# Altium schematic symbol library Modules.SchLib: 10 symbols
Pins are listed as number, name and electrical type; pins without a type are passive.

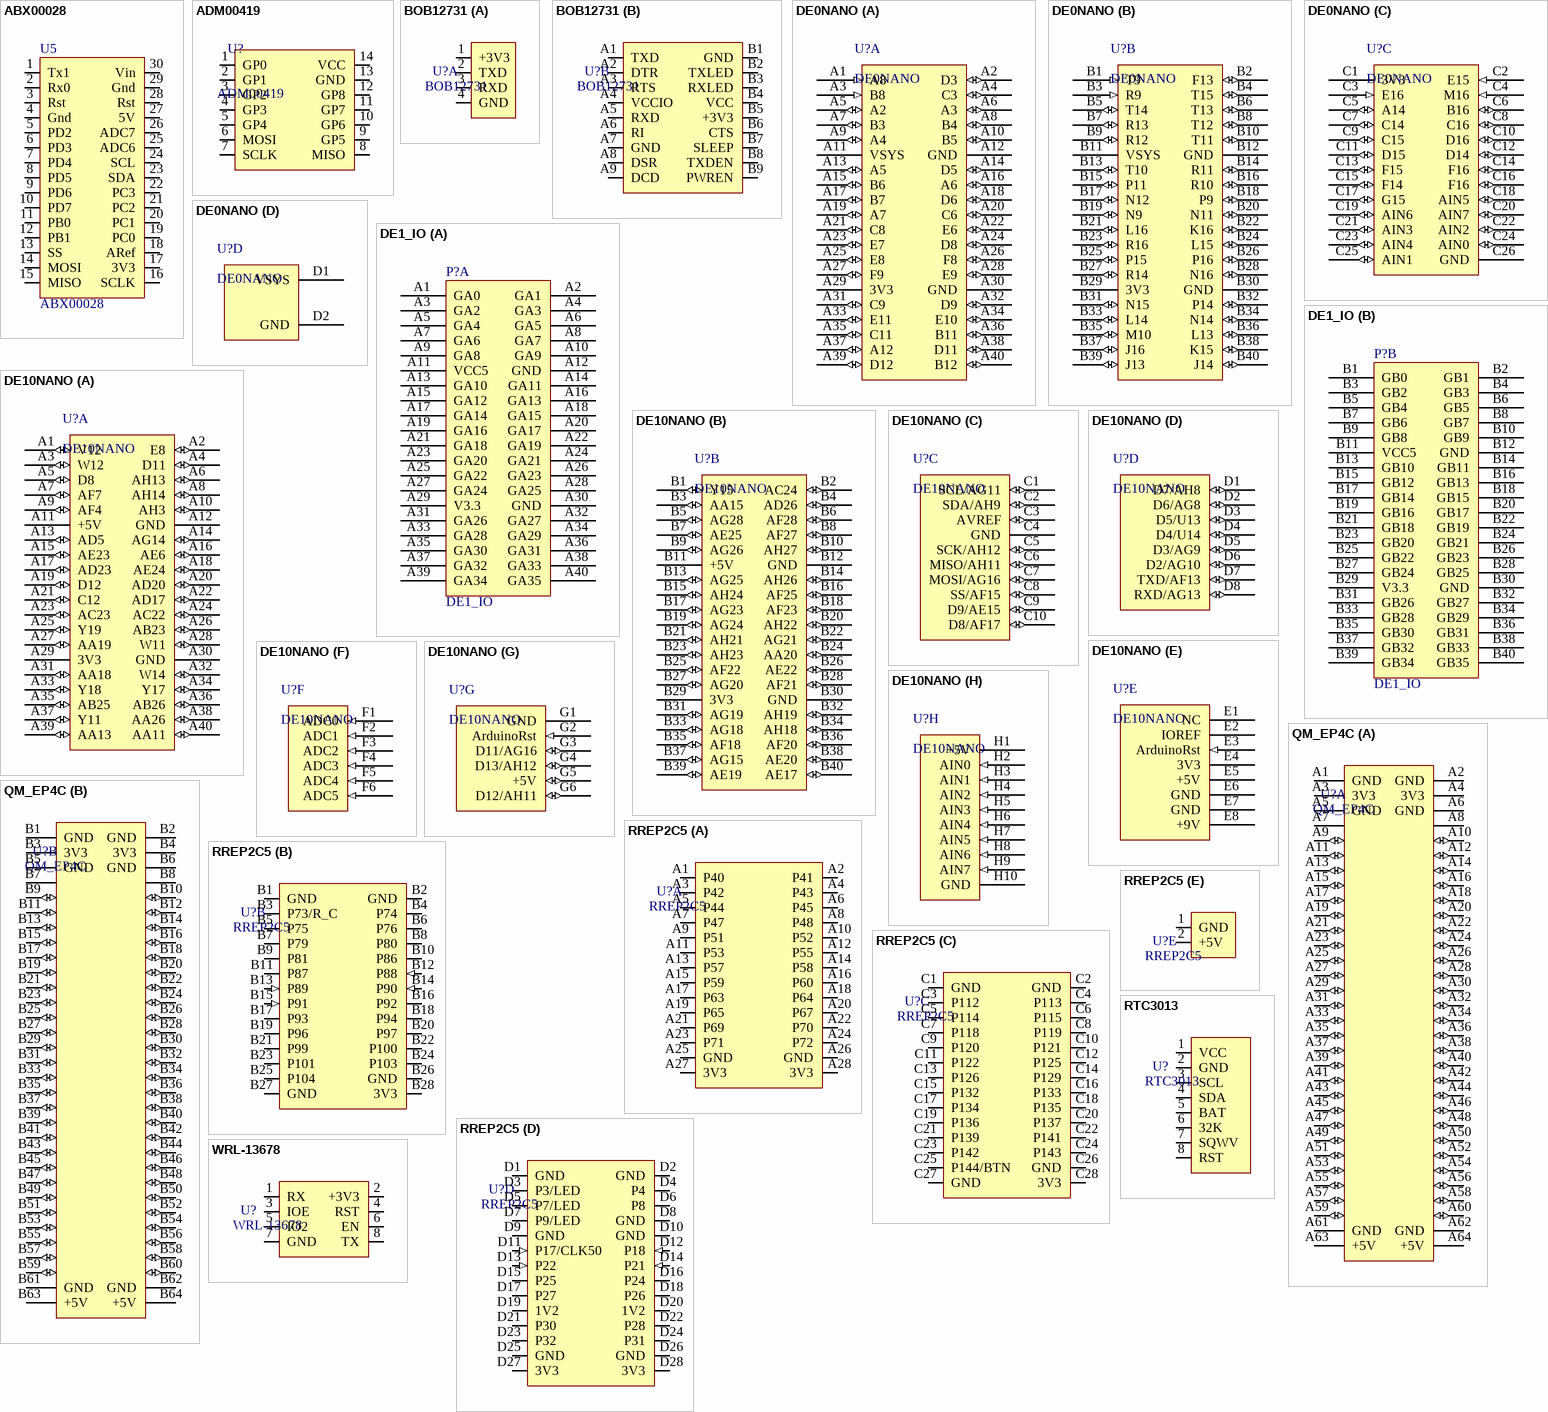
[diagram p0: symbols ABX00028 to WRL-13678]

## ABX00028
designator U5
ATmega4809 Arduino Nano Every AVR® AVR MCU 8-Bit Embedded Evaluation Board; DK PN: 1050-ABX00028-ND
footprint ARDUINO_NANO
pins: 1 Tx1, 2 Rx0, 3 Rst, 4 Gnd (power), 5 PD2, 6 PD3, 7 PD4, 8 PD5, 9 PD6, 10 PD7, 11 PB0, 12 PB1, 13 SS, 14 MOSI, 15 MISO, 16 SCLK, 17 3V3 (power), 18 ARef, 19 PC0, 20 PC1, 21 PC2, 22 PC3, 23 SDA, 24 SCL, 25 ADC6, 26 ADC7, 27 5V (power), 28 Rst, 29 Gnd, 30 Vin

## ADM00419
designator U?
MCP2210 USB to SPI Interface Evaluation Board; DK PN: ADM00419-ND; MFG: Microchip
footprint MCP2210DEV
pins: 1 GP0, 2 GP1, 3 GP2, 4 GP3, 5 GP4, 6 MOSI, 7 SCLK, 8 MISO, 9 GP5, 10 GP6, 11 GP7, 12 GP8, 13 GND, 14 VCC

## BOB12731
designator U?
FT232R USB 2.0 to UART Interface Evaluation Board; MFG: SparkFun; MFG PN: BOB-12731; DK PN: 1568-1195-ND
footprint BOB12731
part A pins: 1 +3V3, 2 TXD, 3 RXD, 4 GND
part B pins: A1 TXD, A2 DTR, A3 RTS, A4 VCCIO, A5 RXD, A6 RI, A7 GND, A8 DSR, A9 DCD, B1 GND, B2 TXLED, B3 RXLED, B4 VCC, B5 +3V3, B6 CTS, B7 SLEEP, B8 TXDEN, B9 PWREN

## DE0NANO
designator U?
footprint DE0NANO
part A pins: A1 A8 (in), A2 D3 (io), A3 B8 (in), A4 C3 (io), A5 A2 (io), A6 A3 (io), A7 B3 (io), A8 B4 (io), A9 A4 (io), A10 B5 (io), A11 VSYS (power), A12 GND (power), A13 A5 (io), A14 D5 (io), A15 B6 (io), A16 A6 (io), A17 B7 (io), A18 D6 (io), A19 A7 (io), A20 C6 (io), A21 C8 (io), A22 E6 (io), A23 E7 (io), A24 D8 (io), A25 E8 (io), A26 F8 (io), A27 F9 (io), A28 E9 (io), A29 3V3 (power), A30 GND (power), A31 C9 (io), A32 D9 (io), A33 E11 (io), A34 E10 (io), A35 C11 (io), A36 B11 (io), A37 A12 (io), A38 D11 (io), A39 D12 (io), A40 B12 (io)
part B pins: B1 T9 (in), B2 F13 (io), B3 R9 (in), B4 T15 (io), B5 T14 (io), B6 T13 (io), B7 R13 (io), B8 T12 (io), B9 R12 (io), B10 T11 (io), B11 VSYS (power), B12 GND (power), B13 T10 (io), B14 R11 (io), B15 P11 (io), B16 R10 (io), B17 N12 (io), B18 P9 (io), B19 N9 (io), B20 N11 (io), B21 L16 (io), B22 K16 (io), B23 R16 (io), B24 L15 (io), B25 P15 (io), B26 P16 (io), B27 R14 (io), B28 N16 (io), B29 3V3 (power), B30 GND (power), B31 N15 (io), B32 P14 (io), B33 L14 (io), B34 N14 (io), B35 M10 (io), B36 L13 (io), B37 J16 (io), B38 K15 (io), B39 J13 (io), B40 J14 (io)
part C pins: C1 3V3 (power), C2 E15 (in), C3 E16 (in), C4 M16 (in), C5 A14 (io), C6 B16 (io), C7 C14 (io), C8 C16 (io), C9 C15 (io), C10 D16 (io), C11 D15 (io), C12 D14 (io), C13 F15 (io), C14 F16 (io), C15 F14 (io), C16 F16 (io), C17 G15 (io), C18 AIN5 (io), C19 AIN6 (io), C20 AIN7 (io), C21 AIN3 (io), C22 AIN2 (io), C23 AIN4 (io), C24 AIN0 (io), C25 AIN1 (io), C26 GND (power)
part D pins: D1 VSYS (power), D2 GND (power)

## DE1_IO
designator P?
footprint DE1_IO
part A pins: A1 GA0, A2 GA1, A3 GA2, A4 GA3, A5 GA4, A6 GA5, A7 GA6, A8 GA7, A9 GA8, A10 GA9, A11 VCC5, A12 GND, A13 GA10, A14 GA11, A15 GA12, A16 GA13, A17 GA14, A18 GA15, A19 GA16, A20 GA17, A21 GA18, A22 GA19, A23 GA20, A24 GA21, A25 GA22, A26 GA23, A27 GA24, A28 GA25, A29 V3.3, A30 GND, A31 GA26, A32 GA27, A33 GA28, A34 GA29, A35 GA30, A36 GA31, A37 GA32, A38 GA33, A39 GA34, A40 GA35
part B pins: B1 GB0, B2 GB1, B3 GB2, B4 GB3, B5 GB4, B6 GB5, B7 GB6, B8 GB7, B9 GB8, B10 GB9, B11 VCC5, B12 GND, B13 GB10, B14 GB11, B15 GB12, B16 GB13, B17 GB14, B18 GB15, B19 GB16, B20 GB17, B21 GB18, B22 GB19, B23 GB20, B24 GB21, B25 GB22, B26 GB23, B27 GB24, B28 GB25, B29 V3.3, B30 GND, B31 GB26, B32 GB27, B33 GB28, B34 GB29, B35 GB30, B36 GB31, B37 GB32, B38 GB33, B39 GB34, B40 GB35

## DE10NANO
designator U?
DE10-NANO CYCLONE V SE SOC KIT; MFG PN: P0496; DK PN: P0496-ND; MFG: Terasic
footprint DE10NANO (DE10 Nano Module)
part A pins: A1 V12 (io), A2 E8 (io), A3 W12 (io), A4 D11 (io), A5 D8 (io), A6 AH13 (io), A7 AF7 (io), A8 AH14 (io), A9 AF4 (io), A10 AH3 (io), A11 +5V (power), A12 GND (power), A13 AD5 (io), A14 AG14 (io), A15 AE23 (io), A16 AE6 (io), A17 AD23 (io), A18 AE24 (io), A19 D12 (io), A20 AD20 (io), A21 C12 (io), A22 AD17 (io), A23 AC23 (io), A24 AC22 (io), A25 Y19 (io), A26 AB23 (io), A27 AA19 (io), A28 W11 (io), A29 3V3 (power), A30 GND (power), A31 AA18 (io), A32 W14 (io), A33 Y18 (io), A34 Y17 (io), A35 AB25 (io), A36 AB26 (io), A37 Y11 (io), A38 AA26 (io), A39 AA13 (io), A40 AA11 (io)
part B pins: B1 Y15 (io), B2 AC24 (io), B3 AA15 (io), B4 AD26 (io), B5 AG28 (io), B6 AF28 (io), B7 AE25 (io), B8 AF27 (io), B9 AG26 (io), B10 AH27 (io), B11 +5V (power), B12 GND (power), B13 AG25 (io), B14 AH26 (io), B15 AH24 (io), B16 AF25 (io), B17 AG23 (io), B18 AF23 (io), B19 AG24 (io), B20 AH22 (io), B21 AH21 (io), B22 AG21 (io), B23 AH23 (io), B24 AA20 (io), B25 AF22 (io), B26 AE22 (io), B27 AG20 (io), B28 AF21 (io), B29 3V3 (power), B30 GND (power), B31 AG19 (io), B32 AH19 (io), B33 AG18 (io), B34 AH18 (io), B35 AF18 (io), B36 AF20 (io), B37 AG15 (io), B38 AE20 (io), B39 AE19 (io), B40 AE17 (io)
part C pins: C1 SCL/AG11 (io), C2 SDA/AH9 (io), C3 AVREF (io), C4 GND (power), C5 SCK/AH12 (io), C6 MISO/AH11 (io), C7 MOSI/AG16 (io), C8 SS/AF15 (io), C9 D9/AE15 (io), C10 D8/AF17 (io)
part D pins: D1 D7/AH8 (io), D2 D6/AG8 (io), D3 D5/U13 (io), D4 D4/U14 (io), D5 D3/AG9 (io), D6 D2/AG10 (io), D7 TXD/AF13 (io), D8 RXD/AG13 (io)
part E pins: E1 NC, E2 IOREF, E3 ArduinoRst (in), E4 3V3 (power), E5 +5V (power), E6 GND (power), E7 GND (power), E8 +9V (power)
part F pins: F1 ADC0 (in), F2 ADC1 (in), F3 ADC2 (in), F4 ADC3 (in), F5 ADC4 (in), F6 ADC5 (in)
part G pins: G1 GND (power), G2 ArduinoRst (in), G3 D11/AG16 (io), G4 D13/AH12 (io), G5 +5V (io), G6 D12/AH11 (io)
part H pins: H1 +5V (power), H2 AIN0 (in), H3 AIN1 (in), H4 AIN2 (in), H5 AIN3 (in), H6 AIN4 (in), H7 AIN5 (in), H8 AIN6 (in), H9 AIN7 (in), H10 GND (power)

## QM_EP4C
designator U?
footprint QMTECH_EP4CE15
part A pins: A1 GND (power), A2 GND (power), A3 3V3 (power), A4 3V3 (power), A5 GND (power), A6 GND (power), A7, A8, A9 (io), A10 (io), A11 (io), A12 (io), A13 (io), A14 (io), A15 (io), A16 (io), A17 (io), A18 (io), A19 (io), A20 (io), A21 (io), A22 (io), A23 (io), A24 (io), A25 (io), A26 (io), A27 (io), A28 (io), A29 (io), A30 (io), A31 (io), A32 (io), A33 (io), A34 (io), A35 (io), A36 (io), A37 (io), A38 (io), A39 (io), A40 (io), A41 (io), A42 (io), A43 (io), A44 (io), A45 (io), A46 (io), A47 (io), A48 (io), A49 (io), A50 (io), A51 (io), A52 (io), A53 (io), A54 (io), A55 (io), A56 (io), A57 (io), A58 (io), A59 (io), A60 (io), A61 GND (power), A62 GND (power), A63 +5V (power), A64 +5V (power)
part B pins: B1 GND (power), B2 GND (power), B3 3V3 (power), B4 3V3 (power), B5 GND (power), B6 GND (power), B7, B8, B9 (io), B10 (io), B11 (io), B12 (io), B13 (io), B14 (io), B15 (io), B16 (io), B17 (io), B18 (io), B19 (io), B20 (io), B21 (io), B22 (io), B23 (io), B24 (io), B25 (io), B26 (io), B27 (io), B28 (io), B29 (io), B30 (io), B31 (io), B32 (io), B33 (io), B34 (io), B35 (io), B36 (io), B37 (io), B38 (io), B39 (io), B40 (io), B41 (io), B42 (io), B43 (io), B44 (io), B45 (io), B46 (io), B47 (io), B48 (io), B49 (io), B50 (io), B51 (io), B52 (io), B53 (io), B54 (io), B55 (io), B56 (io), B57 (io), B58 (io), B59 (io), B60 (io), B61 GND (power), B62 GND (power), B63 +5V (power), B64 +5V (power)

## RREP2C5
designator U?
RioRand EP2C5T144 Altera Cyclone II FPGA Mini Development Board
footprint RR2C5
part A pins: A1 P40 (io), A2 P41 (io), A3 P42 (io), A4 P43 (io), A5 P44 (io), A6 P45 (io), A7 P47 (io), A8 P48 (io), A9 P51 (io), A10 P52 (io), A11 P53 (io), A12 P55 (io), A13 P57 (io), A14 P58 (io), A15 P59 (io), A16 P60 (io), A17 P63 (io), A18 P64 (io), A19 P65 (io), A20 P67 (io), A21 P69 (io), A22 P70 (io), A23 P71 (io), A24 P72 (io), A25 GND (power), A26 GND (power), A27 3V3 (power), A28 3V3 (power)
part B pins: B1 GND (power), B2 GND (power), B3 P73/R_C (io), B4 P74 (io), B5 P75 (io), B6 P76 (io), B7 P79 (io), B8 P80 (io), B9 P81 (io), B10 P86 (io), B11 P87 (io), B12 P88 (in), B13 P89 (in), B14 P90 (in), B15 P91 (in), B16 P92 (io), B17 P93 (io), B18 P94 (io), B19 P96 (io), B20 P97 (io), B21 P99 (io), B22 P100 (io), B23 P101 (io), B24 P103 (io), B25 P104 (io), B26 GND (power), B27 GND (power), B28 3V3 (power)
part C pins: C1 GND (power), C2 GND (power), C3 P112 (io), C4 P113 (io), C5 P114 (io), C6 P115 (io), C7 P118 (io), C8 P119 (io), C9 P120 (io), C10 P121 (io), C11 P122 (io), C12 P125 (io), C13 P126 (io), C14 P129 (io), C15 P132 (io), C16 P133 (io), C17 P134 (io), C18 P135 (io), C19 P136 (io), C20 P137 (io), C21 P139 (io), C22 P141 (io), C23 P142 (io), C24 P143 (io), C25 P144/BTN (io), C26 GND, C27 GND (power), C28 3V3 (power)
part D pins: D1 GND (power), D2 GND (power), D3 P3/LED (io), D4 P4 (io), D5 P7/LED (io), D6 P8 (io), D7 P9/LED (io), D8 GND (power), D9 GND (power), D10 GND (power), D11 P17/CLK50 (in), D12 P18 (in), D13 P22 (in), D14 P21 (in), D15 P25 (io), D16 P24 (io), D17 P27 (io), D18 P26 (io), D19 1V2 (power), D20 1V2 (power), D21 P30 (io), D22 P28 (io), D23 P32 (io), D24 P31 (io), D25 GND (power), D26 GND (power), D27 3V3 (power), D28 3V3 (power)
part E pins: 1 GND (power), 2 +5V (power)

## RTC3013
designator U?
DS3231 Real Time Clock (RTC) Timing Evaluation Board; MFG: AdaFruit; MFG PN: 3013; DK PN: 1528-1598-ND
footprint RTC3013
pins: 1 VCC, 2 GND, 3 SCL, 4 SDA, 5 BAT, 6 32K, 7 SQWV, 8 RST

## WRL-13678
designator U?
WiFi 802.11b/g/n Transceiver Module 2.4GHz ~ 2.48GHz Integrated, Trace Through Hole; MFG: SparkFun; DK PN: 1568-1235-ND
footprint WRL13678
pins: 1 RX, 2 +3V3, 3 IOE, 4 RST, 5 IO2, 6 EN, 7 GND, 8 TX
